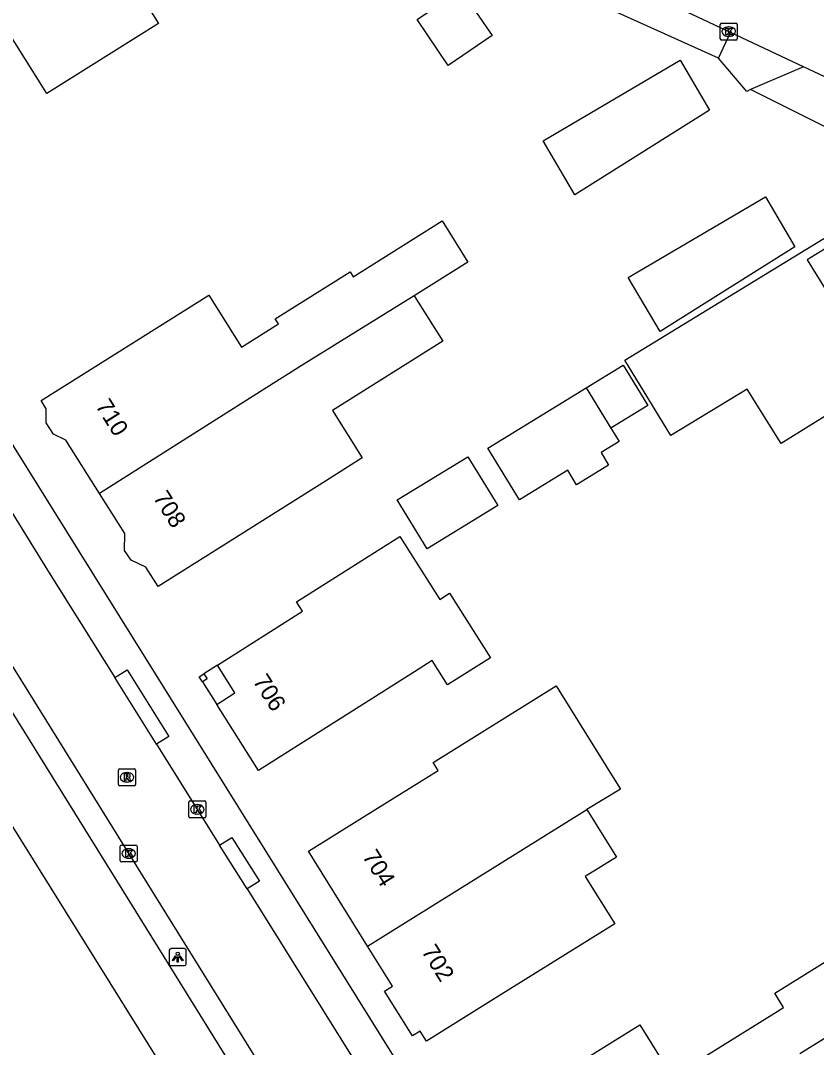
# Model space of a CAD drawing. Extents: x 158838 to 160074, y 386376 to 387776.
# Drawn here: x 159274.8 to 159321.8, y 386502 to 386562.7 of the extents above; entities that cross this region are included whole.
import ezdxf

# ---------------------------------------------------------------- set-up
doc = ezdxf.new("R2010")
doc.units = 0
for name, color, linetype in [('IMGEO_Groenvoorziening', 7, 'Continuous'), ('IMGEO_Kolk', 7, 'Continuous'), ('IMGEO_Lichtpunt', 7, 'Continuous'), ('IMGEO_Pand', 7, 'Continuous'), ('IMGEO_Pand_nummerreeks', 7, 'Continuous'), ('IMGEO_Pand_overbouw', 7, 'Continuous'), ('IMGEO_Rijbaan_lokaal_open', 7, 'Continuous'), ('IMGEO_Rijbaan_regionaal_gesloten', 7, 'Continuous'), ('IMGEO_Rioolput', 7, 'Continuous'), ('IMGEO_Voetpad_open', 7, 'Continuous')]:
    doc.layers.add(name, color=color, linetype=linetype)

msp = doc.modelspace()

# ---------------------------------------------------------------- linework, layer by layer
at = {"layer": 'IMGEO_Groenvoorziening'}
for points in [[(159315.993, 386560.431), (159306.423, 386564.757), (159305.475, 386564.027), (159295.152, 386569.449), (159293.452, 386569.649)], [(159325.094, 386554.983), (159317.883, 386558.586)]]:
    msp.add_lwpolyline(points, dxfattribs=at)
at = {"layer": 'IMGEO_Kolk'}
for p, q in [((159316.1, 386561.577), (159316.1, 386562.429)), ((159316.175, 386562.503), (159317.027, 386562.503)), ((159316.588, 386562.283), (159316.613, 386562.283)), ((159317.101, 386562.429), (159317.101, 386561.577)), ((159317.027, 386561.503), (159316.175, 386561.503)), ((159316.611, 386561.723), (159316.586, 386561.723)), ((159284.785, 386516.573), (159285.637, 386516.573)), ((159284.71, 386515.647), (159284.71, 386516.499)), ((159285.198, 386516.353), (159285.223, 386516.353)), ((159285.711, 386516.499), (159285.711, 386515.647)), ((159285.637, 386515.573), (159284.785, 386515.573)), ((159285.221, 386515.793), (159285.196, 386515.793)), ((159280.664, 386513.04), (159280.664, 386513.892)), ((159280.739, 386513.966), (159281.591, 386513.966)), ((159281.152, 386513.746), (159281.177, 386513.746)), ((159281.665, 386513.892), (159281.665, 386513.04)), ((159281.591, 386512.966), (159280.739, 386512.966)), ((159281.175, 386513.186), (159281.15, 386513.186))]:
    msp.add_line(p, q, dxfattribs=at)
for points in [[(159316.1, 386561.577), (159316.1, 386562.429)], [(159316.175, 386562.503), (159317.027, 386562.503)], [(159316.421, 386562.203), (159316.544, 386562.203), (159316.544, 386562.052), (159316.674, 386562.203), (159316.838, 386562.203), (159316.692, 386562.052), (159316.845, 386561.803), (159316.693, 386561.803), (159316.608, 386561.967), (159316.544, 386561.9), (159316.544, 386561.803), (159316.421, 386561.803), (159316.421, 386562.203)], [(159317.101, 386562.429), (159317.101, 386561.577)], [(159317.027, 386561.503), (159316.175, 386561.503)], [(159284.785, 386516.573), (159285.637, 386516.573)], [(159284.71, 386515.647), (159284.71, 386516.499)], [(159285.031, 386516.273), (159285.154, 386516.273), (159285.154, 386516.122), (159285.284, 386516.273), (159285.448, 386516.273), (159285.302, 386516.122), (159285.455, 386515.873), (159285.303, 386515.873), (159285.218, 386516.037), (159285.154, 386515.97), (159285.154, 386515.873), (159285.031, 386515.873), (159285.031, 386516.273)], [(159285.711, 386516.499), (159285.711, 386515.647)], [(159285.637, 386515.573), (159284.785, 386515.573)], [(159280.664, 386513.04), (159280.664, 386513.892)], [(159280.739, 386513.966), (159281.591, 386513.966)], [(159280.985, 386513.666), (159281.108, 386513.666), (159281.108, 386513.515), (159281.238, 386513.666), (159281.402, 386513.666), (159281.256, 386513.515), (159281.409, 386513.266), (159281.257, 386513.266), (159281.172, 386513.43), (159281.108, 386513.363), (159281.108, 386513.266), (159280.985, 386513.266), (159280.985, 386513.666)], [(159281.665, 386513.892), (159281.665, 386513.04)], [(159281.591, 386512.966), (159280.739, 386512.966)]]:
    msp.add_lwpolyline(points, dxfattribs=at)
for centre, start, end in [((159316.177, 386562.427), 91.55205, 178.44795), ((159316.177, 386562.427), 91.55205, 178.44795), ((159317.025, 386562.427), 1.55205, 88.44795), ((159317.025, 386562.427), 1.55205, 88.44795), ((159316.177, 386561.579), 181.55205, 268.44795), ((159316.177, 386561.579), 181.55205, 268.44795), ((159317.025, 386561.579), 271.55205, 358.44795), ((159317.025, 386561.579), 271.55205, 358.44795), ((159284.787, 386516.497), 91.55205, 178.44795), ((159284.787, 386516.497), 91.55205, 178.44795), ((159285.635, 386516.497), 1.55205, 88.44795), ((159285.635, 386516.497), 1.55205, 88.44795), ((159284.787, 386515.649), 181.55205, 268.44795), ((159284.787, 386515.649), 181.55205, 268.44795), ((159285.635, 386515.649), 271.55205, 358.44795), ((159285.635, 386515.649), 271.55205, 358.44795), ((159280.741, 386513.89), 91.55205, 178.44795), ((159280.741, 386513.89), 91.55205, 178.44795), ((159281.589, 386513.89), 1.55205, 88.44795), ((159281.589, 386513.89), 1.55205, 88.44795), ((159280.741, 386513.042), 181.55205, 268.44795), ((159280.741, 386513.042), 181.55205, 268.44795), ((159281.589, 386513.042), 271.55205, 358.44795), ((159281.589, 386513.042), 271.55205, 358.44795)]:
    msp.add_arc(centre, 0.0765, start, end, dxfattribs=at)
for centre, major_axis, ratio, start_param, end_param in [((159316.587, 386562.003), (-0.387, 0.002), 0.722429, 4.712389, 7.853982), ((159316.612, 386562.003), (-0.39, 0.002), 0.717154, 1.570796, 4.712389), ((159285.197, 386516.073), (-0.387, 0.002), 0.722429, 4.712389, 7.853982), ((159285.222, 386516.073), (-0.39, 0.002), 0.717154, 1.570796, 4.712389), ((159281.151, 386513.466), (-0.387, 0.002), 0.722429, 4.712389, 7.853982), ((159281.176, 386513.466), (-0.39, 0.002), 0.717154, 1.570796, 4.712389)]:
    msp.add_ellipse(centre, major_axis=major_axis, ratio=ratio, start_param=start_param, end_param=end_param, dxfattribs=at)
at = {"layer": 'IMGEO_Lichtpunt'}
for p, q in [((159283.558, 386507.752), (159283.558, 386506.945)), ((159283.558, 386507.752), (159283.558, 386506.945)), ((159284.46, 386507.847), (159283.652, 386507.847)), ((159284.46, 386507.847), (159283.652, 386507.847)), ((159284.554, 386506.945), (159284.554, 386507.752)), ((159284.554, 386506.945), (159284.554, 386507.752)), ((159283.652, 386506.851), (159284.46, 386506.851)), ((159283.652, 386506.851), (159284.46, 386506.851))]:
    msp.add_line(p, q, dxfattribs=at)
for points in [[(159283.932, 386507.416), (159283.971, 386507.388), (159283.783, 386507.126), (159283.745, 386507.153), (159283.932, 386507.416)], [(159284.034, 386507.368), (159284.081, 386507.368), (159284.081, 386507.046), (159284.034, 386507.046), (159284.034, 386507.368)], [(159284.144, 386507.388), (159284.182, 386507.415), (159284.369, 386507.153), (159284.33, 386507.125), (159284.144, 386507.388)]]:
    msp.add_lwpolyline(points, dxfattribs=at)
msp.add_circle((159284.057, 386507.55), 0.0994, dxfattribs=at)
for centre, start, end in [((159283.652, 386507.752), 90, 180), ((159283.652, 386507.752), 90, 180), ((159284.46, 386507.752), 0, 90), ((159284.46, 386507.752), 0, 90), ((159283.652, 386506.945), 180, 270), ((159283.652, 386506.945), 180, 270), ((159284.46, 386506.945), 270, 0), ((159284.46, 386506.945), 270, 360)]:
    msp.add_arc(centre, 0.0946, start, end, dxfattribs=at)
at = {"layer": 'IMGEO_Pand'}
for points in [[(159276.325, 386558.346), (159270.736, 386567.25), (159268.274, 386565.705), (159262.568, 386574.796), (159268.656, 386578.618), (159270.863, 386575.101), (159272.567, 386576.171), (159278.512, 386566.701), (159279.773, 386567.492), (159282.917, 386562.483), (159276.325, 386558.346)], [(159298.191, 386562.717), (159300.777, 386564.478), (159302.625, 386561.766), (159300.039, 386560.005), (159298.191, 386562.717)], [(159313.722, 386560.307), (159315.455, 386557.36), (159307.505, 386552.36), (159305.63, 386555.547), (159313.722, 386560.307)], [(159318.761, 386552.248), (159320.494, 386549.301), (159312.544, 386544.301), (159310.669, 386547.488), (159318.761, 386552.248)], [(159279.444, 386534.724), (159277.456, 386537.883), (159276.716, 386538.221), (159276.291, 386538.901), (159276.295, 386539.728), (159275.987, 386540.218), (159285.886, 386546.448), (159287.821, 386543.372), (159290.009, 386544.749), (159289.821, 386545.047), (159294.233, 386547.824), (159294.42, 386547.526), (159299.666, 386550.828), (159301.198, 386548.394), (159298.028, 386546.399)], [(159322.223, 386549.778), (159322.505, 386549.317), (159321.223, 386548.533), (159322.604, 386546.293), (159323.89, 386547.086), (159326.716, 386548.827), (159326.981, 386548.404), (159327.868, 386546.988), (159328.387, 386547.275), (159330.245, 386544.227), (159319.691, 386537.673), (159317.69, 386540.897), (159313.172, 386538.149), (159310.454, 386542.605), (159322.223, 386549.778)], [(159298.028, 386546.399), (159299.707, 386543.73), (159293.194, 386539.633), (159294.96, 386536.827), (159292.781, 386535.456), (159282.898, 386529.236), (159282.175, 386530.385), (159281.313, 386530.786), (159280.921, 386531.351), (159280.926, 386532.369), (159279.444, 386534.724)], [(159298.028, 386546.399), (159291.51, 386542.365), (159289.32, 386540.99), (159279.444, 386534.724)], [(159308.177, 386540.969), (159310.366, 386542.313), (159311.826, 386539.932), (159309.636, 386538.589)], [(159309.636, 386538.589), (159310.123, 386537.796), (159309.056, 386537.141), (159309.506, 386536.407), (159307.612, 386535.246), (159307.088, 386536.099), (159304.237, 386534.351), (159302.364, 386537.404), (159308.177, 386540.969)], [(159308.177, 386540.969), (159309.636, 386538.589)], [(159301.194, 386536.9), (159302.963, 386534.016), (159298.795, 386531.46), (159297.026, 386534.343), (159301.194, 386536.9)], [(159300.114, 386528.832), (159302.523, 386525.021), (159299.988, 386523.418), (159299.079, 386524.855), (159298.046, 386524.202), (159293.051, 386521.044), (159288.824, 386518.372), (159286.361, 386522.269), (159287.434, 386522.948), (159286.398, 386524.588), (159291.434, 386527.771), (159291.077, 386528.336), (159295.304, 386531.008), (159297.183, 386532.196), (159299.539, 386528.469), (159300.114, 386528.832)], [(159285.594, 386524.08), (159285.787, 386523.776), (159285.516, 386523.605), (159285.324, 386523.909), (159285.594, 386524.08)], [(159295.266, 386507.992), (159291.777, 386513.597), (159296.022, 386516.241), (159299.438, 386518.368), (159299.146, 386518.838), (159306.403, 386523.359), (159306.561, 386523.105), (159309.872, 386517.788), (159310.202, 386517.258), (159308.226, 386516.065)], [(159308.226, 386516.065), (159309.975, 386513.254), (159308.127, 386512.103), (159309.867, 386509.309), (159303, 386505.033), (159298.755, 386502.389), (159298.385, 386502.983), (159297.918, 386502.692), (159296.269, 386505.341), (159296.735, 386505.632), (159295.266, 386507.992)], [(159295.266, 386507.992), (159308.226, 386516.065)], [(159305.584, 386492.249), (159304.392, 386494.162), (159304.125, 386493.996), (159303.779, 386494.551), (159303.001, 386494.6), (159302.037, 386496.149), (159302.305, 386496.917), (159301.945, 386497.495), (159305.966, 386500), (159306.189, 386500.139), (159311.349, 386503.353), (159313.262, 386500.283), (159315.823, 386501.878), (159319.305, 386504.047), (159319.841, 386504.381), (159319.324, 386505.211), (159322.554, 386507.223), (159322.898, 386507.437), (159324.917, 386504.195), (159324.573, 386503.981), (159320.807, 386501.636)]]:
    msp.add_lwpolyline(points, dxfattribs=at)
at = {"layer": 'IMGEO_Pand_overbouw'}
msp.add_lwpolyline([(159286.398, 386524.588), (159285.594, 386524.08), (159285.787, 386523.776), (159285.516, 386523.605), (159286.361, 386522.269), (159287.434, 386522.948)], close=True, dxfattribs=at)
at = {"layer": 'IMGEO_Rijbaan_lokaal_open'}
for points in [[(159316.71, 386561.942), (159294.718, 386572.279)], [(159253.354, 386567.797), (159253.667, 386567.296), (159263.845, 386550.455), (159276.367, 386530.196), (159280.335, 386523.857)], [(159321.009, 386559.932), (159316.71, 386561.942)], [(159326.304, 386557.443), (159321.009, 386559.932)], [(159349.611, 386404.048), (159344.851, 386411.689), (159315.18, 386459.161), (159295.755, 386490.012), (159289.541, 386500), (159260.159, 386547.29), (159256.48, 386553.269)], [(159282.795, 386519.928), (159280.335, 386523.857)], [(159282.795, 386519.928), (159286.529, 386513.965)], [(159288.15, 386511.374), (159286.529, 386513.965)], [(159288.15, 386511.374), (159294.836, 386500.695)]]:
    msp.add_lwpolyline(points, dxfattribs=at)
at = {"layer": 'IMGEO_Rijbaan_regionaal_gesloten'}
for points in [[(159345.081, 386401.546), (159302.571, 386469.726), (159230.609, 386585.166)], [(159255.213, 386552.519), (159258.932, 386546.526), (159259.483, 386545.636), (159287.804, 386500), (159291.106, 386494.697), (159321.596, 386445.895), (159348.223, 386403.503)]]:
    msp.add_lwpolyline(points, dxfattribs=at)
at = {"layer": 'IMGEO_Rioolput'}
for p, q in [((159280.556, 386517.542), (159280.556, 386518.394)), ((159280.631, 386518.468), (159281.483, 386518.468)), ((159281.557, 386518.394), (159281.557, 386517.542)), ((159281.044, 386518.248), (159281.069, 386518.248)), ((159281.483, 386517.468), (159280.631, 386517.468)), ((159281.067, 386517.688), (159281.042, 386517.688))]:
    msp.add_line(p, q, dxfattribs=at)
for points in [[(159280.556, 386517.542), (159280.556, 386518.394)], [(159280.631, 386518.468), (159281.483, 386518.468)], [(159281.557, 386518.394), (159281.557, 386517.542)], [(159281.145, 386518.166), (159280.893, 386518.168), (159280.893, 386517.768)], [(159280.893, 386517.768), (159281.017, 386517.768), (159281.017, 386517.93), (159281.028, 386517.93)], [(159281.071, 386518.087), (159281.017, 386518.087), (159281.017, 386518.006)], [(159281.017, 386518.006), (159281.069, 386518.006)], [(159281.075, 386517.901), (159281.146, 386517.768), (159281.286, 386517.768), (159281.221, 386517.894)], [(159281.483, 386517.468), (159280.631, 386517.468)]]:
    msp.add_lwpolyline(points, dxfattribs=at)
for centre, radius, start, end in [((159280.633, 386518.392), 0.0765, 91.55205, 178.44795), ((159280.633, 386518.392), 0.0765, 91.55205, 178.44795), ((159281.481, 386518.392), 0.0765, 1.55205, 88.44795), ((159281.481, 386518.392), 0.0765, 1.55205, 88.44795), ((159281.027, 386517.877), 0.0533, 26.02933, 88.69889), ((159281.053, 386518.195), 0.19, 274.7715, 282.96867), ((159281.077, 386517.991), 0.0964, 77.00612, 93.18647), ((159281.091, 386518.048), 0.0378, 276.66336, 79.67722), ((159281.144, 386518.056), 0.109, 350.36119, 89.41601), ((159281.142, 386518.056), 0.112, 277.58423, 350.98172), ((159281.126, 386517.841), 0.108, 29.51342, 73.79051), ((159280.633, 386517.544), 0.0765, 181.55205, 268.44795), ((159280.633, 386517.544), 0.0765, 181.55205, 268.44795), ((159281.481, 386517.544), 0.0765, 271.55205, 358.44795), ((159281.481, 386517.544), 0.0765, 271.55205, 358.44795)]:
    msp.add_arc(centre, radius, start, end, dxfattribs=at)
for centre, major_axis, ratio, start_param, end_param in [((159281.043, 386517.968), (-0.387, 0.002), 0.722429, 4.712389, 7.853982), ((159281.068, 386517.968), (-0.39, 0.002), 0.717154, 1.570796, 4.712389)]:
    msp.add_ellipse(centre, major_axis=major_axis, ratio=ratio, start_param=start_param, end_param=end_param, dxfattribs=at)
at = {"layer": 'IMGEO_Voetpad_open'}
for points in [[(159242.178, 386588.93), (159258.715, 386562.329), (159267.344, 386548.729), (159297.72, 386500), (159350.037, 386416.075)], [(159315.993, 386560.431), (159316.71, 386561.942)], [(159317.883, 386558.586), (159317.672, 386558.468), (159315.993, 386560.431)], [(159321.009, 386559.932), (159317.883, 386558.586)], [(159280.335, 386523.857), (159281.064, 386524.313), (159283.524, 386520.384), (159282.795, 386519.928)], [(159286.529, 386513.965), (159287.258, 386514.421), (159288.879, 386511.83), (159288.15, 386511.374)]]:
    msp.add_lwpolyline(points, dxfattribs=at)

# ---------------------------------------------------------------- texts
at = {"layer": 'IMGEO_Pand_nummerreeks'}
for s, rotation, p in [('710', 302.18283, (159279.165, 386539.901)), ('708', 302.18283, (159282.572, 386534.488)), ('706', 302.29742, (159288.467, 386523.653)), ('704', 301.90781, (159294.932, 386513.298)), ('702', 301.90781, (159298.42, 386507.696))]:
    msp.add_text(s, height=1, rotation=rotation, dxfattribs=at).set_placement(p)

doc.saveas('drawing.dxf')
